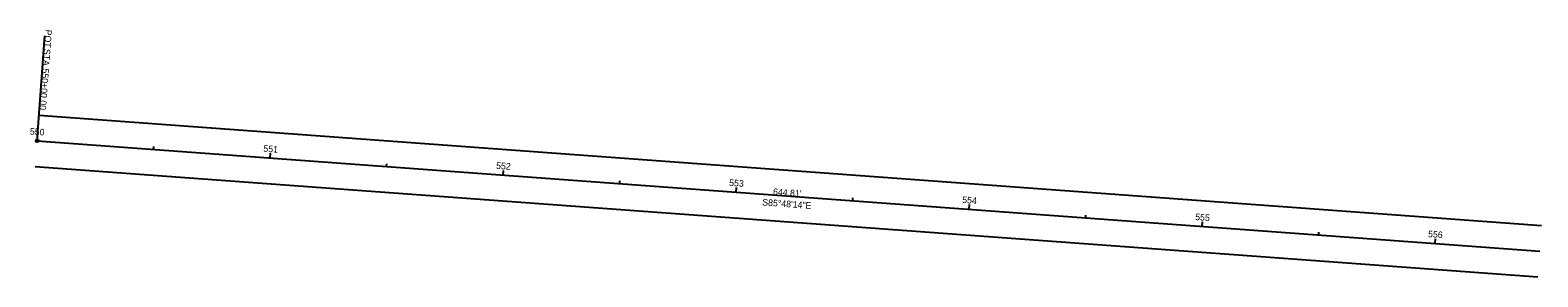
# Model space of a CAD drawing. Extents: x 1898481 to 1901152, y 703119 to 703373.
# Drawn here: x 1898481 to 1899126, y 703267 to 703373 of the extents above; entities that cross this region are included whole.
import ezdxf

# ---------------------------------------------------------------- set-up
doc = ezdxf.new("R2010")
doc.units = 0
for name, color, linetype in [('_CIVIL_CONSTRUCTION', 7, 'Continuous'), ('DT_P_Terrain_Boundary', 7, 'Continuous'), ('DT_P_Triangles', 7, 'Continuous'), ('PF_X_Ground_Line', 7, 'Continuous'), ('PV_P_EOP', 7, 'Continuous'), ('SC_Scratch1', 7, 'Continuous')]:
    doc.layers.add(name, color=color, linetype=linetype)

msp = doc.modelspace()

# ---------------------------------------------------------------- linework, layer by layer
at = {"layer": '_CIVIL_CONSTRUCTION'}
msp.add_line((1898483.64, 703325.5), (1898486.93, 703370.38), dxfattribs=at)
msp.add_circle((1898483.64, 703325.5), 0.6, dxfattribs=at)
at = {"layer": 'DT_P_Triangles'}
for p, q in [((1898483.64, 703325.5), (1898483.78, 703327.5)), ((1898533.5, 703321.85), (1898533.59, 703323.04)), ((1898583.37, 703318.19), (1898583.52, 703320.18)), ((1898633.24, 703314.53), (1898633.32, 703315.72)), ((1898683.1, 703310.87), (1898683.25, 703312.86)), ((1898732.97, 703307.21), (1898733.06, 703308.41)), ((1898782.83, 703303.55), (1898782.98, 703305.55)), ((1898832.7, 703299.89), (1898832.79, 703301.09)), ((1898882.57, 703296.24), (1898882.71, 703298.23)), ((1898932.43, 703292.58), (1898932.52, 703293.77)), ((1898982.3, 703288.92), (1898982.44, 703290.91)), ((1899032.16, 703285.26), (1899032.25, 703286.46)), ((1899082.03, 703281.6), (1899082.18, 703283.6))]:
    msp.add_line(p, q, dxfattribs=at)
at = {"layer": 'PV_P_EOP'}
for p, q in [((1898484.44, 703336.47), (1899127.53, 703289.29)), ((1898482.83, 703314.53), (1899125.91, 703267.35))]:
    msp.add_line(p, q, dxfattribs=at)
at = {"layer": 'SC_Scratch1'}
msp.add_line((1898483.64, 703325.5), (1899126.72, 703278.32), dxfattribs=at)

# ---------------------------------------------------------------- texts
at = {"layer": '_CIVIL_CONSTRUCTION'}
for s, p in [('POT', (1898487.18, 703373.17)), (' STA. ', (1898486.65, 703365.99)), ('550+00.00', (1898485.96, 703356.56))]:
    msp.add_text(s, height=2.8, rotation=265.80384, dxfattribs=at).set_placement(p)
at = {"layer": 'DT_P_Terrain_Boundary'}
msp.add_text("644.81'", height=2.8, rotation=355.80384, dxfattribs=at).set_placement((1898798.52, 703302.44))
at = {"layer": 'DT_P_Triangles'}
for s, p in [('550', (1898480.48, 703328.24)), ('551', (1898580.41, 703320.91)), ('552', (1898680.01, 703313.6)), ('553', (1898779.75, 703306.29)), ('554', (1898879.49, 703298.97)), ('555', (1898979.19, 703291.65)), ('556', (1899078.86, 703284.34))]:
    msp.add_text(s, height=2.8, rotation=355.80384, dxfattribs=at).set_placement(p)
at = {"layer": 'PF_X_Ground_Line'}
msp.add_text('S85°48\'14"E', height=2.8, rotation=355.80384, dxfattribs=at).set_placement((1898793.92, 703297.93))

doc.saveas('drawing.dxf')
